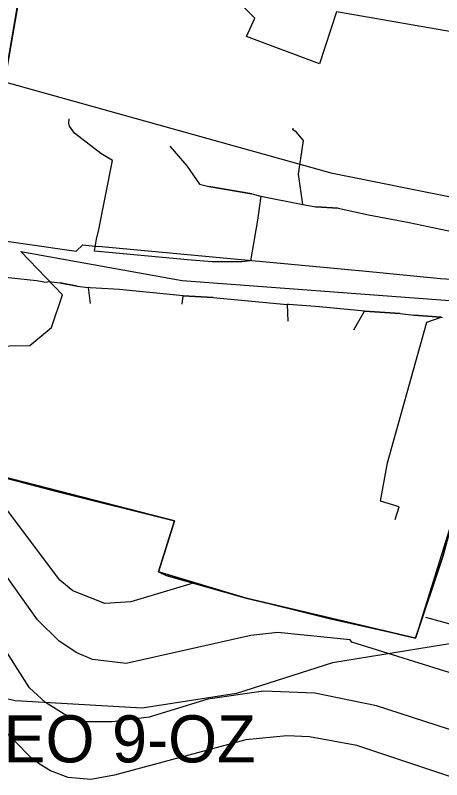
# Model space of a CAD drawing. Extents: x -662500 to -655523, y -1056000 to -1049993.
# Drawn here: x -660539 to -660421.4, y -1052282.8 to -1052071.9 of the extents above; entities that cross this region are included whole.
import ezdxf

# ---------------------------------------------------------------- set-up
doc = ezdxf.new("R2010")
doc.units = 0
for name, color, linetype in [('Vrstva 1', 7, 'Continuous'), ('Vrstva 20', 7, 'Continuous'), ('Vrstva 24', 7, 'Continuous'), ('Vrstva 45', 7, 'Continuous'), ('Vrstva 48', 7, 'Continuous'), ('Vrstva 5', 7, 'Continuous'), ('Vrstva 6', 7, 'Continuous'), ('Vrstva 7', 7, 'Continuous')]:
    doc.layers.add(name, color=color, linetype=linetype)

msp = doc.modelspace()

# ---------------------------------------------------------------- linework, layer by layer
at = {"layer": 'Vrstva 1'}
for points in [[(-660554.23, -1052145.33), (-660549.33, -1052132.73), (-660543.74, -1052100.07), (-660537.55, -1052064.32), (-660536.99, -1052061.08), (-660533.42, -1052042.18), (-660529.4, -1052017.99), (-660526.37, -1052016.17), (-660497.13, -1051998.48), (-660473.03, -1051983.91), (-660444.41, -1051966.62), (-660443.04, -1051941.53), (-660409.35, -1051945.41), (-660388.98, -1051947.77), (-660362.03, -1051950.34), (-660358.34, -1051950.81), (-660318.47, -1051954.21), (-660286.74, -1051956.91), (-660259.81, -1051958.85)], [(-660495.07, -1052211.29), (-660517.03, -1052205.91), (-660527.17, -1052203.32), (-660534.27, -1052201.47), (-660536.66, -1052200.85), (-660578.14, -1052190.03), (-660572.16, -1052170.84), (-660563.85, -1052144.19), (-660554.23, -1052145.33)], [(-660408.77, -1052283.62), (-660402.29, -1052259.33), (-660394.65, -1052237.63), (-660389.99, -1052217.3), (-660396.18, -1052215.3), (-660414.84, -1052209.49), (-660417.67, -1052208.59), (-660421.03, -1052221.2), (-660427.21, -1052239.6), (-660428.58, -1052243.68), (-660452.47, -1052238.38), (-660475.36, -1052232.69), (-660497.36, -1052226.43)], [(-660497.36, -1052226.43), (-660499.48, -1052225.45), (-660495.07, -1052211.29)]]:
    msp.add_lwpolyline(points, dxfattribs=at)
at = {"layer": 'Vrstva 20'}
for points in [[(-660693, -1052092.39), (-660549.33, -1052132.73), (-660529.4, -1052017.99), (-660444.65, -1051966.93), (-660443.04, -1051941.53), (-660507.57, -1051940.01), (-660528.33, -1051935.72), (-660624.47, -1051996.3), (-660674.23, -1052051.96)], [(-660611.17, -1052274.32), (-660487.99, -1052312.15), (-660486.82, -1052314.01), (-660462.36, -1052329.02), (-660459.17, -1052336.8), (-660433.93, -1052352.12), (-660408.77, -1052283.62), (-660402.29, -1052259.33), (-660394.65, -1052237.63), (-660389.99, -1052217.3), (-660417.67, -1052208.59), (-660428.58, -1052243.68), (-660475.36, -1052232.69), (-660499.48, -1052225.45), (-660495.07, -1052211.29), (-660578.14, -1052190.03), (-660563.85, -1052144.19), (-660586.5, -1052144.05), (-660704.06, -1052109.9), (-660743.35, -1052235.04)]]:
    msp.add_lwpolyline(points, close=True, dxfattribs=at)
at = {"layer": 'Vrstva 24'}
for points in [[(-660328, -1052135), (-660352, -1052135.5), (-660451.5, -1052115.5), (-660661, -1052057), (-660695, -1052042.5), (-660723, -1052024.5), (-660747.5, -1052000), (-660756.5, -1051991), (-660777.56, -1051972.71)], [(-660417.5, -1052245), (-660451.5, -1052250.5), (-660478, -1052259), (-660504, -1052263), (-660539, -1052261), (-660579, -1052252), (-660609, -1052240.5), (-660650.5, -1052213), (-660664.5, -1052194.5), (-660663.5, -1052181.5), (-660652.5, -1052172), (-660629.5, -1052164.5), (-660535, -1052163), (-660529, -1052158), (-660526, -1052149), (-660537.5, -1052137), (-660493, -1052145), (-660399.5, -1052152)]]:
    msp.add_lwpolyline(points, dxfattribs=at)
at = {"layer": 'Vrstva 45'}
for p, q in [((-660524.2, -1052101.58), (-660524.1, -1052100.38)), ((-660524.2, -1052101.58), (-660524.1, -1052100.38)), ((-660473.76, -1052121.12), (-660485.62, -1052119.1)), ((-660473.76, -1052121.12), (-660485.62, -1052119.1)), ((-660471.3, -1052121.8), (-660459.7, -1052124.03)), ((-660471.3, -1052121.8), (-660459.7, -1052124.03)), ((-660449.9, -1052125.06), (-660456.15, -1052124.67)), ((-660449.9, -1052125.06), (-660456.15, -1052124.67)), ((-660476.51, -1052139.83), (-660484.74, -1052139.9)), ((-660476.51, -1052139.83), (-660484.74, -1052139.9)), ((-660521.94, -1052146.63), (-660526.61, -1052145.69)), ((-660521.94, -1052146.63), (-660526.61, -1052145.69)), ((-660518.89, -1052146.94), (-660518.34, -1052151.37)), ((-660518.89, -1052146.94), (-660518.34, -1052151.37)), ((-660510.29, -1052147.47), (-660518.36, -1052147.04)), ((-660510.29, -1052147.47), (-660518.36, -1052147.04)), ((-660492.99, -1052151.55), (-660492.67, -1052149.21)), ((-660492.99, -1052151.55), (-660492.67, -1052149.21)), ((-660484.44, -1052149.72), (-660492.67, -1052149.21)), ((-660484.44, -1052149.72), (-660492.67, -1052149.21)), ((-660464.01, -1052151.68), (-660463.81, -1052156.27)), ((-660464.01, -1052151.68), (-660463.81, -1052156.27)), ((-660455.08, -1052152.33), (-660463.52, -1052151.69)), ((-660455.08, -1052152.33), (-660463.52, -1052151.69)), ((-660445.59, -1052158.59), (-660442.67, -1052153.44)), ((-660445.59, -1052158.59), (-660442.67, -1052153.44)), ((-660432.84, -1052154.12), (-660442.67, -1052153.44)), ((-660432.84, -1052154.12), (-660442.67, -1052153.44)), ((-660421.53, -1052155.16), (-660429.05, -1052154.56)), ((-660421.53, -1052155.16), (-660429.05, -1052154.56)), ((-660421.53, -1052155.16), (-660421.22, -1052155.19)), ((-660421.53, -1052155.16), (-660421.22, -1052155.19))]:
    msp.add_line(p, q, dxfattribs=at)
for points in [[(-660471.3, -1052121.8), (-660472.2, -1052128.41), (-660474.12, -1052139.64), (-660476.51, -1052139.83), (-660484.74, -1052139.9), (-660491.54, -1052139.28), (-660517.15, -1052136.97), (-660516.61, -1052133.65), (-660515.96, -1052130.96), (-660512.22, -1052111.92), (-660515.37, -1052109.98), (-660522.67, -1052104.41), (-660524.04, -1052102.47), (-660524.2, -1052101.58)], [(-660471.3, -1052121.8), (-660472.2, -1052128.41), (-660474.12, -1052139.64), (-660476.51, -1052139.83), (-660484.74, -1052139.9), (-660491.54, -1052139.28), (-660517.15, -1052136.97), (-660516.61, -1052133.65), (-660515.96, -1052130.96), (-660512.22, -1052111.92), (-660515.37, -1052109.98), (-660522.67, -1052104.41), (-660524.04, -1052102.47), (-660524.2, -1052101.58)], [(-660459.7, -1052124.03), (-660460.85, -1052115.69), (-660459.5, -1052106.42), (-660461.49, -1052103.98), (-660462.47, -1052103.46), (-660462.39, -1052103.03)], [(-660459.7, -1052124.03), (-660460.85, -1052115.69), (-660459.5, -1052106.42), (-660461.49, -1052103.98), (-660462.47, -1052103.46), (-660462.39, -1052103.03)], [(-660496.42, -1052107.92), (-660491.71, -1052113.37), (-660488.23, -1052118.46), (-660485.62, -1052119.1), (-660473.76, -1052121.12), (-660471.3, -1052121.8)], [(-660496.42, -1052107.92), (-660491.71, -1052113.37), (-660488.23, -1052118.46), (-660485.62, -1052119.1), (-660473.76, -1052121.12), (-660471.3, -1052121.8)], [(-660459.7, -1052124.03), (-660456.15, -1052124.67), (-660449.9, -1052125.06), (-660441.55, -1052126.88), (-660430.39, -1052129.05), (-660416.38, -1052131.95)], [(-660459.7, -1052124.03), (-660456.15, -1052124.67), (-660449.9, -1052125.06), (-660441.55, -1052126.88), (-660430.39, -1052129.05), (-660416.38, -1052131.95)], [(-660565.6, -1052125.72), (-660548.55, -1052133.15), (-660522.21, -1052136.92), (-660520.4, -1052135.15), (-660516.13, -1052135.6)], [(-660565.6, -1052125.72), (-660548.55, -1052133.15), (-660522.21, -1052136.92), (-660520.4, -1052135.15), (-660516.13, -1052135.6)], [(-660450.08, -1052141.84), (-660451.03, -1052141.75), (-660516.13, -1052135.6)], [(-660450.08, -1052141.84), (-660451.03, -1052141.75), (-660516.13, -1052135.6)], [(-660564.37, -1052143.61), (-660562.65, -1052141.61), (-660557.78, -1052141.59), (-660552.06, -1052142.58), (-660543.55, -1052143.9), (-660533.12, -1052144.98), (-660530.51, -1052145.48), (-660529.78, -1052145.27), (-660526.61, -1052145.69), (-660521.94, -1052146.63), (-660518.89, -1052146.94)], [(-660564.37, -1052143.61), (-660562.65, -1052141.61), (-660557.78, -1052141.59), (-660552.06, -1052142.58), (-660543.55, -1052143.9), (-660533.12, -1052144.98), (-660530.51, -1052145.48), (-660529.78, -1052145.27), (-660526.61, -1052145.69), (-660521.94, -1052146.63), (-660518.89, -1052146.94)], [(-660443.11, -1052142.49), (-660447.25, -1052142.1), (-660450.08, -1052141.84)], [(-660443.11, -1052142.49), (-660447.25, -1052142.1), (-660450.08, -1052141.84)], [(-660412.15, -1052145.73), (-660415.93, -1052144.97), (-660421.76, -1052144.56), (-660443.11, -1052142.49)], [(-660412.15, -1052145.73), (-660415.93, -1052144.97), (-660421.76, -1052144.56), (-660443.11, -1052142.49)], [(-660492.67, -1052149.21), (-660510.29, -1052147.47), (-660518.36, -1052147.04), (-660518.89, -1052146.94)], [(-660492.67, -1052149.21), (-660510.29, -1052147.47), (-660518.36, -1052147.04), (-660518.89, -1052146.94)], [(-660492.67, -1052149.21), (-660484.44, -1052149.72), (-660464.01, -1052151.68)], [(-660492.67, -1052149.21), (-660484.44, -1052149.72), (-660464.01, -1052151.68)], [(-660442.67, -1052153.44), (-660455.08, -1052152.33), (-660463.52, -1052151.69), (-660464.01, -1052151.68)], [(-660442.67, -1052153.44), (-660455.08, -1052152.33), (-660463.52, -1052151.69), (-660464.01, -1052151.68)], [(-660442.67, -1052153.44), (-660432.84, -1052154.12), (-660429.05, -1052154.56), (-660421.53, -1052155.16)], [(-660442.67, -1052153.44), (-660432.84, -1052154.12), (-660429.05, -1052154.56), (-660421.53, -1052155.16)], [(-660434.19, -1052210.92), (-660433.11, -1052207.46), (-660438.23, -1052205.95), (-660436.37, -1052195.34), (-660425.46, -1052156.53), (-660421.53, -1052155.16)], [(-660434.19, -1052210.92), (-660433.11, -1052207.46), (-660438.23, -1052205.95), (-660436.37, -1052195.34), (-660425.46, -1052156.53), (-660421.53, -1052155.16)]]:
    msp.add_lwpolyline(points, dxfattribs=at)
at = {"layer": 'Vrstva 48'}
msp.add_lwpolyline([(-660538.48, -1052060.8), (-660532.95, -1052023.05), (-660419.09, -1051950.78), (-660293.14, -1051956.25), (-660296.06, -1052023.47), (-660343.35, -1052021.42), (-660365.15, -1052017.09), (-660400.6, -1052017.74), (-660407.59, -1052078.33), (-660450.39, -1052070.9), (-660455.11, -1052085.25), (-660475.19, -1052077.7), (-660472.89, -1052072.61), (-660501.35, -1052043.96), (-660517.23, -1052041.74), (-660522.98, -1052061.96), (-660537.85, -1052062.06)], dxfattribs=at)
at = {"layer": 'Vrstva 5'}
msp.add_lwpolyline([(-660757.57, -1052084.94), (-660618.97, -1052129.25), (-660588.97, -1052137.76), (-660563.85, -1052144.19), (-660578.14, -1052190.03), (-660527.17, -1052203.32), (-660495.07, -1052211.29), (-660499.48, -1052225.45), (-660497.36, -1052226.43), (-660475.36, -1052232.69), (-660428.58, -1052243.68), (-660421.03, -1052221.2), (-660417.67, -1052208.59), (-660396.18, -1052215.3), (-660389.99, -1052217.3), (-660394.65, -1052237.63), (-660402.29, -1052259.33), (-660408.77, -1052283.62)], dxfattribs=at)
at = {"layer": 'Vrstva 6'}
msp.add_lwpolyline([(-660462.36, -1052329.02), (-660459.17, -1052336.8), (-660433.93, -1052352.12), (-660409.6, -1052285.62), (-660402.29, -1052259.33), (-660394.65, -1052237.63), (-660389.99, -1052217.3), (-660417.67, -1052208.59), (-660421.03, -1052221.2), (-660428.58, -1052243.68), (-660452.47, -1052238.38), (-660475.36, -1052232.69), (-660499.48, -1052225.45), (-660495.07, -1052211.29), (-660578.14, -1052190.03), (-660563.85, -1052144.19), (-660586.5, -1052144.05), (-660704.06, -1052109.9), (-660743.35, -1052235.04), (-661096.01, -1052128.52), (-661110.22, -1052170.21), (-660506.09, -1052352.23), (-660487.99, -1052312.15)], close=True, dxfattribs=at)
at = {"layer": 'Vrstva 7'}
for p, q in [((-660526.7, -1052227.69), (-660546.69, -1052201.19)), ((-660532.92, -1052238.69), (-660546.54, -1052219.47)), ((-660523.16, -1052230.67), (-660526.7, -1052227.69)), ((-660489.98, -1052228.53), (-660507.15, -1052233.64)), ((-660514.35, -1052234.17), (-660523.16, -1052230.67)), ((-660507.15, -1052233.64), (-660514.35, -1052234.17)), ((-660535.07, -1052257.45), (-660546.26, -1052239.88)), ((-660526.94, -1052244.56), (-660532.92, -1052238.69)), ((-660397.48, -1052245.66), (-660425.8, -1052238.04)), ((-660466.62, -1052242.15), (-660473.99, -1052243)), ((-660446.63, -1052244.13), (-660466.62, -1052242.15)), ((-660473.99, -1052243), (-660508.42, -1052250.65)), ((-660446.14, -1052244.77), (-660446.63, -1052244.13)), ((-660522.05, -1052247.76), (-660526.94, -1052244.56)), ((-660413.05, -1052255.11), (-660446.14, -1052244.77)), ((-660517.72, -1052249.58), (-660522.05, -1052247.76)), ((-660508.42, -1052250.65), (-660517.72, -1052249.58)), ((-660530.67, -1052261.42), (-660535.07, -1052257.45)), ((-660470.58, -1052258.3), (-660485.89, -1052260.57)), ((-660456.41, -1052258.87), (-660470.58, -1052258.3)), ((-660439.41, -1052262.41), (-660456.41, -1052258.87)), ((-660485.89, -1052260.57), (-660502.05, -1052265.53)), ((-660525.57, -1052264.68), (-660530.67, -1052261.42)), ((-660406, -1052273.22), (-660439.41, -1052262.41)), ((-660520.47, -1052266.8), (-660525.57, -1052264.68)), ((-660534.64, -1052276.73), (-660544.99, -1052266.24)), ((-660512.25, -1052266.8), (-660520.47, -1052266.8)), ((-660502.05, -1052265.53), (-660512.25, -1052266.8)), ((-660464.07, -1052270.63), (-660475.4, -1052271.77)), ((-660457.83, -1052270.92), (-660464.07, -1052270.63)), ((-660444.79, -1052273.32), (-660457.83, -1052270.92)), ((-660475.4, -1052271.77), (-660511.68, -1052281.54)), ((-660415.6, -1052283.1), (-660444.79, -1052273.32)), ((-660532.14, -1052278.6), (-660534.64, -1052276.73)), ((-660529.3, -1052280.34), (-660532.14, -1052278.6)), ((-660524.44, -1052282.11), (-660529.3, -1052280.34)), ((-660518.2, -1052282.68), (-660524.44, -1052282.11)), ((-660511.68, -1052281.54), (-660518.2, -1052282.68))]:
    msp.add_line(p, q, dxfattribs=at)

# ---------------------------------------------------------------- texts
at = {"layer": 'Vrstva 20'}
msp.add_text('PEO 9-OZ', height=13, dxfattribs=at).set_placement((-660553.86, -1052277.99))

doc.saveas('drawing.dxf')
